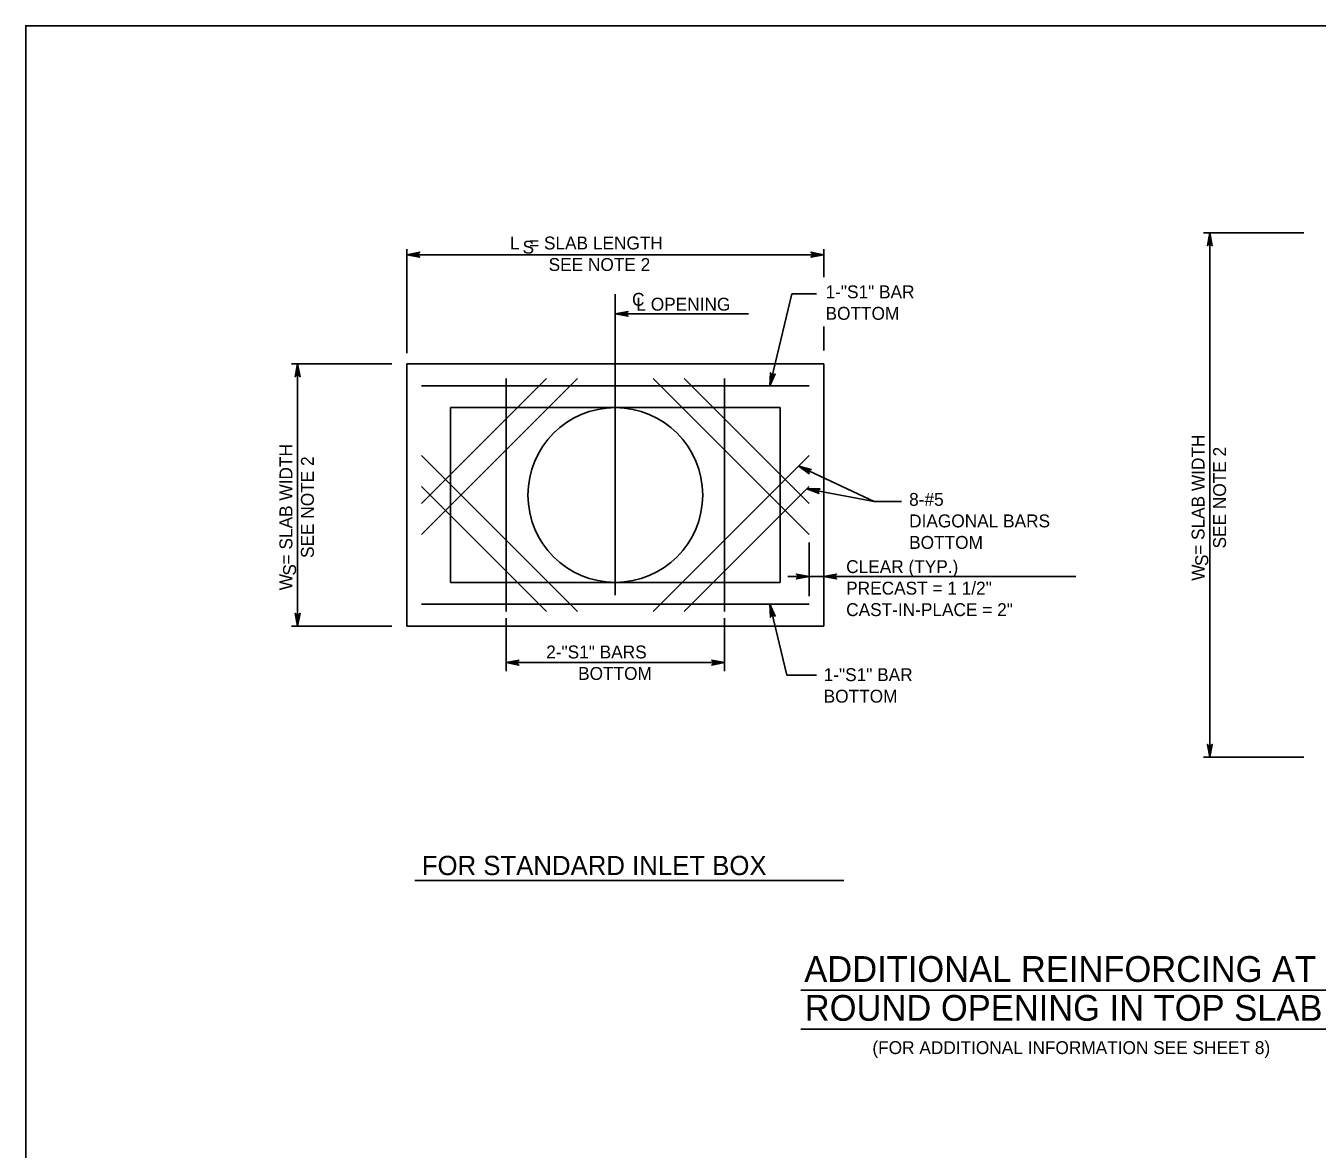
# Model space of a CAD drawing. Extents: x -6420 to 49575, y -4552 to 11624.
# Drawn here: x 1985 to 2970, y 8769 to 9626 of the extents above; entities that cross this region are included whole.
import ezdxf

# ---------------------------------------------------------------- set-up
doc = ezdxf.new("R2010")
doc.units = 0
doc.layers.add('1', color=7, linetype='Continuous')

msp = doc.modelspace()

# ---------------------------------------------------------------- linework, layer by layer
at = {"layer": '1'}
for p, q in [((2883.69, 9467.95), (2960.22, 9467.95)), ((2888.35, 9467.95), (2888.35, 9067.94)), ((2275.82, 9455.39), (2275.82, 9376.21)), ((2275.82, 9451.28), (2593.88, 9451.28)), ((2593.88, 9455.39), (2593.88, 9434.03)), ((2434.85, 9191.54), (2434.85, 9421.2)), ((2569.58, 9421.5), (2552.7, 9351.28)), ((2588.24, 9421.5), (2569.58, 9421.5)), ((2536.35, 9406.22), (2434.85, 9406.22)), ((2593.88, 9396.55), (2593.88, 9378.12)), ((2187.83, 9367.95), (2264.35, 9367.95)), ((2192.49, 9367.95), (2192.49, 9167.94)), ((2405.89, 9356.83), (2286.93, 9237.88)), ((2382.32, 9356.83), (2286.93, 9261.45)), ((2582.77, 9351.28), (2286.93, 9351.28)), ((2351.52, 9179.06), (2351.52, 9356.83)), ((2582.77, 9237.88), (2463.81, 9356.83)), ((2582.77, 9261.45), (2487.39, 9356.83)), ((2518.19, 9179.06), (2518.19, 9356.83)), ((2405.89, 9179.06), (2286.93, 9298.01)), ((2582.77, 9298.01), (2463.81, 9179.06)), ((2632.41, 9262.94), (2574.75, 9289.99)), ((2382.32, 9179.06), (2286.93, 9274.44)), ((2582.77, 9274.44), (2487.39, 9179.06)), ((2580.98, 9272.65), (2632.41, 9262.94)), ((2632.41, 9262.94), (2653.2, 9262.94)), ((2582.77, 9231.69), (2582.77, 9190.93)), ((2566.41, 9205.84), (2786.09, 9205.84)), ((2582.77, 9184.61), (2286.93, 9184.61)), ((2565.67, 9130.66), (2552.7, 9184.61)), ((2351.52, 9173.94), (2351.52, 9133.7)), ((2518.19, 9173.94), (2518.19, 9133.7)), ((2187.83, 9167.94), (2264.35, 9167.94)), ((2351.52, 9140.11), (2518.19, 9140.11)), ((2588.32, 9130.66), (2565.67, 9130.66)), ((2883.69, 9067.94), (2960.22, 9067.94)), ((2282.01, 8973.82), (2609.22, 8973.82)), ((2576.46, 8890.28), (3065.61, 8890.28)), ((2576.46, 8860.59), (3065.61, 8860.59))]:
    msp.add_line(p, q, dxfattribs=at)
for points in [[(4563.89, 7775.47), (4563.89, 9625.87), (1985.15, 9625.87), (1985.15, 7775.47), (4563.89, 7775.47), (4563.89, 7861.95), (3907.72, 7861.95), (3907.72, 8074.15), (4563.89, 8074.15), (4563.89, 8169.17), (3907.72, 8169.17), (3907.72, 7775.47), (4166.25, 7775.47), (4166.25, 7861.95), (4166.25, 7775.47), (4418.88, 7775.47), (4418.88, 7861.95), (4418.88, 7821.54), (4563.89, 7821.54)], [(2888.35, 9467.95), (2890.18, 9458.16), (2889.92, 9458.54), (2889.66, 9458.92), (2889.33, 9459.11), (2889.01, 9459.31), (2888.68, 9459.36), (2888.35, 9459.42), (2888.02, 9459.36), (2887.69, 9459.31), (2887.37, 9459.11), (2887.04, 9458.92), (2886.78, 9458.54), (2886.51, 9458.16), (2888.35, 9467.95), (2886.78, 9458.54), (2887.04, 9458.92), (2888.35, 9467.95), (2887.37, 9459.11), (2887.69, 9459.31), (2888.35, 9467.95), (2888.02, 9459.36), (2888.35, 9459.42), (2888.35, 9467.95), (2888.68, 9459.36), (2889.01, 9459.31), (2888.35, 9467.95), (2889.33, 9459.11), (2889.66, 9458.92), (2888.35, 9467.95), (2889.92, 9458.54)], [(2275.82, 9451.28), (2285.61, 9453.12), (2285.23, 9452.85), (2284.85, 9452.59), (2284.66, 9452.27), (2284.46, 9451.94), (2284.41, 9451.61), (2284.35, 9451.28), (2284.41, 9450.95), (2284.46, 9450.62), (2284.66, 9450.3), (2284.85, 9449.97), (2285.23, 9449.71), (2285.61, 9449.45), (2275.82, 9451.28), (2285.23, 9449.71), (2284.85, 9449.97), (2275.82, 9451.28), (2284.66, 9450.3), (2284.46, 9450.62), (2275.82, 9451.28), (2284.41, 9450.95), (2284.35, 9451.28), (2275.82, 9451.28), (2284.41, 9451.61), (2284.46, 9451.94), (2275.82, 9451.28), (2284.66, 9452.27), (2284.85, 9452.59), (2275.82, 9451.28), (2285.23, 9452.85)], [(2593.88, 9451.28), (2584.09, 9449.45), (2584.47, 9449.71), (2584.85, 9449.97), (2585.04, 9450.3), (2585.24, 9450.62), (2585.29, 9450.95), (2585.35, 9451.28), (2585.29, 9451.61), (2585.24, 9451.94), (2585.04, 9452.27), (2584.85, 9452.59), (2584.47, 9452.85), (2584.09, 9453.12), (2593.88, 9451.28), (2584.47, 9452.85), (2584.85, 9452.59), (2593.88, 9451.28), (2585.04, 9452.27), (2585.24, 9451.94), (2593.88, 9451.28), (2585.29, 9451.61), (2585.35, 9451.28), (2593.88, 9451.28), (2585.29, 9450.95), (2585.24, 9450.62), (2593.88, 9451.28), (2585.04, 9450.3), (2584.85, 9449.97), (2593.88, 9451.28), (2584.47, 9449.71)], [(2434.85, 9406.22), (2444.64, 9408.05), (2444.26, 9407.79), (2443.88, 9407.53), (2443.69, 9407.2), (2443.49, 9406.87), (2443.44, 9406.55), (2443.38, 9406.22), (2443.44, 9405.89), (2443.49, 9405.56), (2443.69, 9405.23), (2443.88, 9404.91), (2444.26, 9404.64), (2444.64, 9404.38), (2434.85, 9406.22), (2444.26, 9404.64), (2443.88, 9404.91), (2434.85, 9406.22), (2443.69, 9405.23), (2443.49, 9405.56), (2434.85, 9406.22), (2443.44, 9405.89), (2443.38, 9406.22), (2434.85, 9406.22), (2443.44, 9406.55), (2443.49, 9406.87), (2434.85, 9406.22), (2443.69, 9407.2), (2443.88, 9407.53), (2434.85, 9406.22), (2444.26, 9407.79)], [(2192.49, 9367.95), (2194.32, 9358.16), (2194.06, 9358.54), (2193.8, 9358.92), (2193.47, 9359.11), (2193.14, 9359.3), (2192.82, 9359.36), (2192.49, 9359.42), (2192.16, 9359.36), (2191.83, 9359.3), (2191.5, 9359.11), (2191.18, 9358.92), (2190.91, 9358.54), (2190.65, 9358.16), (2192.49, 9367.95), (2190.91, 9358.54), (2191.18, 9358.92), (2192.49, 9367.95), (2191.5, 9359.11), (2191.83, 9359.3), (2192.49, 9367.95), (2192.16, 9359.36), (2192.49, 9359.42), (2192.49, 9367.95), (2192.82, 9359.36), (2193.14, 9359.3), (2192.49, 9367.95), (2193.47, 9359.11), (2193.8, 9358.92), (2192.49, 9367.95), (2194.06, 9358.54)], [(2552.7, 9351.28), (2553.21, 9361.22), (2553.37, 9360.8), (2553.54, 9360.37), (2553.81, 9360.1), (2554.09, 9359.84), (2554.39, 9359.71), (2554.7, 9359.57), (2555.03, 9359.55), (2555.36, 9359.53), (2555.73, 9359.64), (2556.09, 9359.76), (2556.43, 9360.06), (2556.77, 9360.37), (2552.7, 9351.28), (2556.43, 9360.06), (2556.09, 9359.76), (2552.7, 9351.28), (2555.73, 9359.64), (2555.36, 9359.53), (2552.7, 9351.28), (2555.03, 9359.55), (2554.7, 9359.57), (2552.7, 9351.28), (2554.39, 9359.71), (2554.09, 9359.84), (2552.7, 9351.28), (2553.81, 9360.1), (2553.54, 9360.37), (2552.7, 9351.28), (2553.37, 9360.8)], [(2574.75, 9289.99), (2584.39, 9287.5), (2583.94, 9287.42), (2583.48, 9287.35), (2583.17, 9287.13), (2582.85, 9286.92), (2582.66, 9286.64), (2582.47, 9286.37), (2582.38, 9286.05), (2582.3, 9285.73), (2582.33, 9285.35), (2582.37, 9284.97), (2582.6, 9284.57), (2582.83, 9284.18), (2574.75, 9289.99), (2582.6, 9284.57), (2582.37, 9284.97), (2574.75, 9289.99), (2582.33, 9285.35), (2582.3, 9285.73), (2574.75, 9289.99), (2582.38, 9286.05), (2582.47, 9286.37), (2574.75, 9289.99), (2582.66, 9286.64), (2582.85, 9286.92), (2574.75, 9289.99), (2583.17, 9287.13), (2583.48, 9287.35), (2574.75, 9289.99), (2583.94, 9287.42)], [(2580.98, 9272.65), (2590.93, 9272.64), (2590.51, 9272.45), (2590.1, 9272.26), (2589.84, 9271.98), (2589.59, 9271.69), (2589.48, 9271.38), (2589.36, 9271.07), (2589.35, 9270.73), (2589.35, 9270.4), (2589.48, 9270.04), (2589.61, 9269.68), (2589.93, 9269.36), (2590.25, 9269.03), (2580.98, 9272.65), (2589.93, 9269.36), (2589.61, 9269.68), (2580.98, 9272.65), (2589.48, 9270.04), (2589.35, 9270.4), (2580.98, 9272.65), (2589.35, 9270.73), (2589.36, 9271.07), (2580.98, 9272.65), (2589.48, 9271.38), (2589.59, 9271.69), (2580.98, 9272.65), (2589.84, 9271.98), (2590.1, 9272.26), (2580.98, 9272.65), (2590.51, 9272.45)], [(2582.77, 9205.84), (2572.98, 9204.01), (2573.36, 9204.27), (2573.74, 9204.53), (2573.93, 9204.86), (2574.12, 9205.19), (2574.18, 9205.51), (2574.24, 9205.84), (2574.18, 9206.17), (2574.12, 9206.5), (2573.93, 9206.83), (2573.74, 9207.15), (2573.36, 9207.41), (2572.98, 9207.68), (2582.77, 9205.84), (2573.36, 9207.41), (2573.74, 9207.15), (2582.77, 9205.84), (2573.93, 9206.83), (2574.12, 9206.5), (2582.77, 9205.84), (2574.18, 9206.17), (2574.24, 9205.84), (2582.77, 9205.84), (2574.18, 9205.51), (2574.12, 9205.19), (2582.77, 9205.84), (2573.93, 9204.86), (2573.74, 9204.53), (2582.77, 9205.84), (2573.36, 9204.27)], [(2593.88, 9205.84), (2603.67, 9207.68), (2603.29, 9207.41), (2602.91, 9207.15), (2602.72, 9206.83), (2602.52, 9206.5), (2602.47, 9206.17), (2602.41, 9205.84), (2602.47, 9205.51), (2602.52, 9205.19), (2602.72, 9204.86), (2602.91, 9204.53), (2603.29, 9204.27), (2603.67, 9204.01), (2593.88, 9205.84), (2603.29, 9204.27), (2602.91, 9204.53), (2593.88, 9205.84), (2602.72, 9204.86), (2602.52, 9205.19), (2593.88, 9205.84), (2602.47, 9205.51), (2602.41, 9205.84), (2593.88, 9205.84), (2602.47, 9206.17), (2602.52, 9206.5), (2593.88, 9205.84), (2602.72, 9206.83), (2602.91, 9207.15), (2593.88, 9205.84), (2603.29, 9207.41)], [(2552.7, 9184.61), (2553.21, 9174.67), (2553.37, 9175.1), (2553.54, 9175.52), (2553.81, 9175.79), (2554.09, 9176.05), (2554.39, 9176.19), (2554.7, 9176.32), (2555.03, 9176.34), (2555.36, 9176.36), (2555.73, 9176.25), (2556.09, 9176.14), (2556.43, 9175.83), (2556.77, 9175.52), (2552.7, 9184.61), (2556.43, 9175.83), (2556.09, 9176.14), (2552.7, 9184.61), (2555.73, 9176.25), (2555.36, 9176.36), (2552.7, 9184.61), (2555.03, 9176.34), (2554.7, 9176.32), (2552.7, 9184.61), (2554.39, 9176.19), (2554.09, 9176.05), (2552.7, 9184.61), (2553.81, 9175.79), (2553.54, 9175.52), (2552.7, 9184.61), (2553.37, 9175.1)], [(2192.49, 9167.94), (2190.65, 9177.73), (2190.91, 9177.35), (2191.18, 9176.98), (2191.5, 9176.78), (2191.83, 9176.59), (2192.16, 9176.53), (2192.49, 9176.47), (2192.82, 9176.53), (2193.14, 9176.59), (2193.47, 9176.78), (2193.8, 9176.98), (2194.06, 9177.35), (2194.32, 9177.73), (2192.49, 9167.94), (2194.06, 9177.35), (2193.8, 9176.98), (2192.49, 9167.94), (2193.47, 9176.78), (2193.14, 9176.59), (2192.49, 9167.94), (2192.82, 9176.53), (2192.49, 9176.47), (2192.49, 9167.94), (2192.16, 9176.53), (2191.83, 9176.59), (2192.49, 9167.94), (2191.5, 9176.78), (2191.18, 9176.98), (2192.49, 9167.94), (2190.91, 9177.35)], [(2351.52, 9140.11), (2361.3, 9141.94), (2360.92, 9141.68), (2360.55, 9141.42), (2360.35, 9141.09), (2360.16, 9140.76), (2360.1, 9140.44), (2360.05, 9140.11), (2360.1, 9139.78), (2360.16, 9139.45), (2360.35, 9139.12), (2360.55, 9138.8), (2360.92, 9138.53), (2361.3, 9138.27), (2351.52, 9140.11), (2360.92, 9138.53), (2360.55, 9138.8), (2351.52, 9140.11), (2360.35, 9139.12), (2360.16, 9139.45), (2351.52, 9140.11), (2360.1, 9139.78), (2360.05, 9140.11), (2351.52, 9140.11), (2360.1, 9140.44), (2360.16, 9140.76), (2351.52, 9140.11), (2360.35, 9141.09), (2360.55, 9141.42), (2351.52, 9140.11), (2360.92, 9141.68)], [(2518.19, 9140.11), (2508.4, 9138.27), (2508.78, 9138.53), (2509.15, 9138.8), (2509.35, 9139.12), (2509.54, 9139.45), (2509.6, 9139.78), (2509.66, 9140.11), (2509.6, 9140.44), (2509.54, 9140.76), (2509.35, 9141.09), (2509.15, 9141.42), (2508.78, 9141.68), (2508.4, 9141.94), (2518.19, 9140.11), (2508.78, 9141.68), (2509.15, 9141.42), (2518.19, 9140.11), (2509.35, 9141.09), (2509.54, 9140.76), (2518.19, 9140.11), (2509.6, 9140.44), (2509.66, 9140.11), (2518.19, 9140.11), (2509.6, 9139.78), (2509.54, 9139.45), (2518.19, 9140.11), (2509.35, 9139.12), (2509.15, 9138.8), (2518.19, 9140.11), (2508.78, 9138.53)], [(2888.35, 9067.94), (2886.51, 9077.73), (2886.78, 9077.35), (2887.04, 9076.97), (2887.37, 9076.78), (2887.69, 9076.58), (2888.02, 9076.53), (2888.35, 9076.47), (2888.68, 9076.53), (2889.01, 9076.58), (2889.33, 9076.78), (2889.66, 9076.97), (2889.92, 9077.35), (2890.18, 9077.73), (2888.35, 9067.94), (2889.92, 9077.35), (2889.66, 9076.97), (2888.35, 9067.94), (2889.33, 9076.78), (2889.01, 9076.58), (2888.35, 9067.94), (2888.68, 9076.53), (2888.35, 9076.47), (2888.35, 9067.94), (2888.02, 9076.53), (2887.69, 9076.58), (2888.35, 9067.94), (2887.37, 9076.78), (2887.04, 9076.97), (2888.35, 9067.94), (2886.78, 9077.35)]]:
    msp.add_lwpolyline(points, dxfattribs=at)
for points in [[(2275.82, 9367.95), (2593.88, 9367.95), (2593.88, 9167.94), (2275.82, 9167.94)], [(2309.15, 9201.28), (2560.55, 9201.28), (2560.55, 9334.61), (2309.15, 9334.61)]]:
    msp.add_lwpolyline(points, close=True, dxfattribs=at)
msp.add_circle((2434.85, 9267.95), 66.67, dxfattribs=at)

# ---------------------------------------------------------------- texts
for s, height, p in [('L  = SLAB LENGTH', 9.8425, (2354.43, 9455.28)), ('S', 9.84, (2364.09, 9452.12)), ('SEE NOTE 2', 9.843, (2383.96, 9438.87)), ('1-"S1" BAR', 9.843, (2595.24, 9418.02)), ('C', 9.84, (2447.6, 9412.31)), ('L OPENING', 9.843, (2450.94, 9408.6)), ('BOTTOM', 9.843, (2595.24, 9401.62)), ('8-#5', 9.843, (2658.99, 9259.7)), ('DIAGONAL BARS', 9.8425, (2658.99, 9243.29)), ('BOTTOM', 9.843, (2658.99, 9226.89)), ('CLEAR (TYP.)', 9.8425, (2610.96, 9208.41)), ('PRECAST = 1 1/2"', 9.8425, (2610.96, 9192.01)), ('CAST-IN-PLACE = 2"', 9.8425, (2610.96, 9175.6)), ('2-"S1" BARS', 9.8425, (2382.13, 9143.32)), ('BOTTOM', 9.843, (2406.46, 9126.92)), ('1-"S1" BAR', 9.843, (2593.81, 9126)), ('BOTTOM', 9.843, (2593.81, 9109.59)), ('FOR STANDARD INLET BOX', 14.6898, (2287.22, 8978.04)), ('ADDITIONAL REINFORCING AT', 19.685, (2578.99, 8896.57)), ('ROUND OPENING IN TOP SLAB', 19.685, (2579.38, 8866.89)), ('(FOR ADDITIONAL INFORMATION SEE SHEET 8)', 9.8425, (2630.96, 8841.51))]:
    msp.add_text(s, height=height, dxfattribs=at).set_placement(p)
for s, height, p in [('W  = SLAB WIDTH', 9.8425, (2884.35, 9202.57)), ('W  = SLAB WIDTH', 9.8425, (2188.49, 9195.3)), ('SEE NOTE 2', 9.843, (2900.75, 9227.18)), ('SEE NOTE 2', 9.843, (2204.89, 9219.91)), ('S', 9.84, (2887.14, 9213.73)), ('S', 9.84, (2191.28, 9206.46))]:
    msp.add_text(s, height=height, rotation=90, dxfattribs=at).set_placement(p)

doc.saveas('drawing.dxf')
